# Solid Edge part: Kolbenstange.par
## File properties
Username: bmolnar
Dokumentum tartalom típus: 0
Author: bmolnar
Last saved by: bmolnar
Revision: 82
Sűrűség: 0,000 kg/m^3
Pontosság: 0,990
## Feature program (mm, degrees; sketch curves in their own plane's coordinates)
base feature "unnamed BaseFeature 1"
sketch for "unnamed Protrusion 1" plane through (61.5, 0, 0) normal (1, 0, 0) x-axis (0, 0, 1)
  circle centre (0, 0) radius 40
extrude "unnamed Protrusion 1" add finite 19.5 along +normal
sketch for "Kihúzás_2" plane through (61.5, 0, 0) normal (1, 0, 0) x-axis (0, 0, 1)
  circle centre (0, 0) radius 40
extrude "Kihúzás_2" add finite 4.5 along -normal
thread "unnamed Thread 1"
chamfer "Letörés_1" setback 3.3  SetBackValue2 = 20 deg
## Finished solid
Body 1: solid body, 17 faces, 23 edges, 8 vertices.
  Faces by surface: plane 8, cylinder 4, torus 3, cone 2
  Edges by curve: circle 13, line 6, ellipse 2, intersection 2
Bounding box of the edges (mm; curved faces can reach further): 96.000 x 80.000 x 80.000, from (-15, -40, -40) to (81, 40, 40).
Cylindrical faces by radius (mm): R6.75 x1, R8 x1, R10 x1, R40 x1
Conical faces (half-angle, radius in mm at the cone's reference point): 20 deg R6.7989 x1, 60 deg R7.475 x1
Toroidal faces (ring radius, tube radius in mm): R7.15 r0.4 x2, R8.2 r1.8 x1
Planar faces by outward normal: +x 1, +y 1, -x 3, -y 1, oblique 2
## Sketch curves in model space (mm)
circle centre (61.5, 0, 0) radius 40
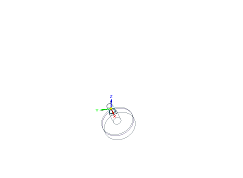
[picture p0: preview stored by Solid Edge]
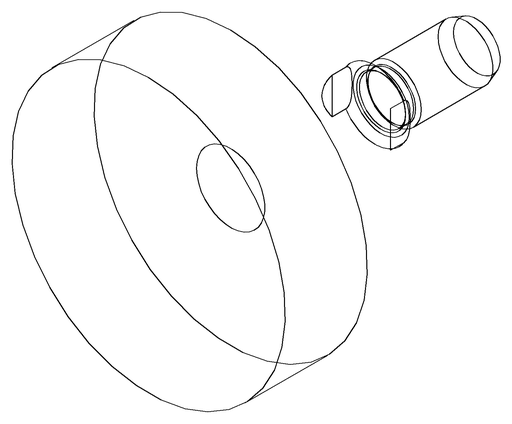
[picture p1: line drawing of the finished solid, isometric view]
